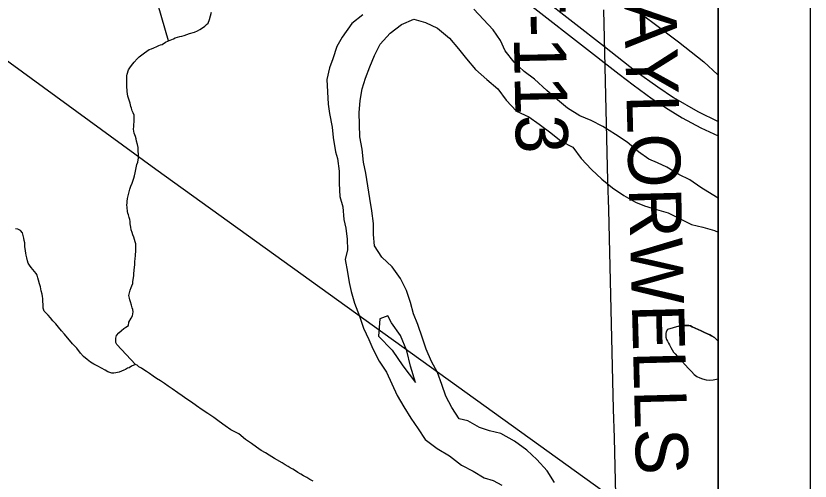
# Model space of a CAD drawing. Extents: x -6.1 to 38, y -7.7 to 22.
# Drawn here: x 8.136 to 9, y 18.932 to 19.438 of the extents above; entities that cross this region are included whole.
import ezdxf

# ---------------------------------------------------------------- set-up
doc = ezdxf.new("R2010")
doc.units = 0
for name, color, linetype in [('GM_X_Corporation', 7, 'Continuous'), ('GM_X_County_Road', 7, 'Continuous'), ('GM_X_Major_River', 7, 'Continuous'), ('GM_X_Minor_Lake', 7, 'Continuous'), ('GM_X_Minor_River', 7, 'Continuous'), ('GM_X_Rail_Line', 7, 'Continuous'), ('GM_X_Township_Road', 7, 'Continuous'), ('GM_X_Township_Road_Text', 7, 'Continuous'), ('GM_X_US_Route', 7, 'Continuous'), ('SH_Data', 7, 'Continuous')]:
    doc.layers.add(name, color=color, linetype=linetype)

msp = doc.modelspace()

# ---------------------------------------------------------------- linework, layer by layer
at = {"layer": 'GM_X_Corporation'}
for points in [[(8.9, 14.85918), (8.9, 19.87135), (8.53815, 19.88018), (8.02661, 19.88922), (8.02125, 19.70471), (8.02079, 19.68982), (8.0189, 19.62846), (7.99279, 18.77986), (7.97287, 17.92154), (7.97183, 17.87641), (7.95308, 17.06692), (7.95307, 17.06643), (7.93594, 16.3267), (7.92512, 16.10977), (7.91657, 15.91251), (7.90988, 15.74002), (7.90533, 15.62285), (7.88899, 15.0865), (7.88923, 14.89059), (8.1023, 14.88375), (8.27757, 14.87811), (8.6137, 14.86789)], [(8.9, 14.68725), (8.9, 19.53649), (8.77571, 19.53237), (8.77312, 19.53228), (6.99327, 19.47331), (6.99349, 19.46054), (7.03821, 16.8882), (7.05054, 16.17866), (7.07262, 15.21743), (7.07601, 15.03919), (7.07603, 15.03845), (7.07902, 14.88093), (7.08348, 14.64684), (7.55487, 14.65733), (8.5875, 14.68029)]]:
    msp.add_lwpolyline(points, close=True, dxfattribs=at)
at = {"layer": 'GM_X_County_Road'}
msp.add_lwpolyline([(8.55884, 19.53655), (8.56055, 19.55141), (8.56401, 19.57385), (8.57684, 19.57004), (8.60433, 19.55739), (8.63363, 19.54294), (8.66313, 19.5289), (8.68078, 19.52027), (8.69356, 19.51458), (8.70948, 19.50683), (8.72684, 19.49888), (8.73496, 19.49599), (8.74219, 19.49218), (8.75161, 19.48737), (8.76586, 19.47794), (8.79435, 19.45647), (8.82886, 19.43058), (8.85695, 19.40972), (8.88424, 19.38804), (8.89909, 19.3742), (8.9, 19.37329)], dxfattribs=at)
at = {"layer": 'GM_X_Major_River'}
for points in [[(8.9, 19.23953), (8.89332, 19.24361), (8.88117, 19.25111), (8.86901, 19.25938), (8.85725, 19.26537), (8.84397, 19.27326), (8.8341, 19.27812), (8.82462, 19.28185), (8.81323, 19.29013), (8.80106, 19.30067), (8.78815, 19.30893), (8.77448, 19.31756), (8.76196, 19.32393), (8.74945, 19.32916), (8.73616, 19.33742), (8.72513, 19.34646), (8.71372, 19.35662), (8.70003, 19.36905), (8.68901, 19.37733), (8.67798, 19.3875), (8.66807, 19.39995), (8.66308, 19.4113), (8.65507, 19.42262), (8.64478, 19.43394), (8.63412, 19.44525)], [(8.51353, 19.43917), (8.50149, 19.42962), (8.491, 19.41476), (8.48501, 19.40448), (8.48056, 19.39118), (8.47722, 19.3813), (8.47428, 19.36876), (8.47567, 19.3417), (8.47721, 19.33185), (8.4799, 19.31669), (8.48107, 19.3057), (8.48376, 19.29016), (8.48568, 19.28259), (8.48761, 19.26894), (8.48765, 19.25567)], [(8.62755, 18.9973), (8.61808, 18.99952), (8.61006, 19.01198), (8.60355, 19.02408), (8.59931, 19.03695), (8.59469, 19.04981), (8.58818, 19.06191), (8.58242, 19.07514), (8.57818, 19.08725), (8.57318, 19.10201), (8.56856, 19.11374), (8.56508, 19.12623), (8.56083, 19.1391), (8.55432, 19.15233), (8.54517, 19.16479), (8.53413, 19.17534), (8.52611, 19.18781), (8.5249, 19.19993), (8.52482, 19.21207), (8.52322, 19.22571), (8.52086, 19.23935), (8.51888, 19.25299), (8.51653, 19.26663), (8.51418, 19.27875), (8.51258, 19.29277), (8.51022, 19.30641), (8.50976, 19.31968), (8.5093, 19.33257), (8.51035, 19.34586), (8.51254, 19.35839), (8.51624, 19.37017), (8.52108, 19.38233), (8.52591, 19.39488), (8.53226, 19.40706), (8.54315, 19.41926), (8.55557, 19.42844), (8.56877, 19.43421), (8.58165, 19.43088), (8.59455, 19.42452), (8.60747, 19.4136), (8.61738, 19.4019), (8.62615, 19.39134), (8.63605, 19.37964), (8.64822, 19.36872), (8.66039, 19.35856), (8.66917, 19.3461), (8.68059, 19.33442), (8.69386, 19.32805), (8.70526, 19.32016), (8.7178, 19.31076), (8.7292, 19.30173), (8.74172, 19.29498), (8.75088, 19.2829), (8.7623, 19.27084), (8.77333, 19.26029), (8.78512, 19.25088), (8.79727, 19.24262), (8.81018, 19.23511), (8.81965, 19.23138), (8.83292, 19.22729), (8.84542, 19.22358), (8.85794, 19.21759), (8.87084, 19.21085), (8.88333, 19.20789), (8.89583, 19.20456), (8.9, 19.20242)], [(8.48765, 19.25567), (8.48845, 19.24127), (8.4915, 19.23028), (8.49268, 19.21626), (8.49498, 19.20679), (8.49614, 19.19504), (8.49656, 19.18328), (8.49406, 19.17281), (8.4968, 19.15917), (8.49838, 19.14781), (8.50072, 19.13796), (8.5042, 19.12547), (8.50959, 19.11109), (8.51421, 19.09823), (8.51996, 19.08575), (8.52419, 19.07553), (8.53108, 19.0623), (8.5391, 19.05022), (8.54485, 19.03774), (8.55061, 19.02488), (8.55787, 19.01241), (8.56551, 19.00032), (8.57353, 18.98862), (8.58117, 18.97691), (8.59409, 18.96713), (8.60775, 18.95925), (8.62068, 18.9491), (8.63357, 18.94273), (8.64534, 18.93522), (8.65519, 18.93225), (8.66468, 18.92738)], [(8.53192, 19.1082), (8.53052, 19.0896), (8.54537, 19.07415), (8.55683, 19.05716), (8.57056, 19.03904)], [(8.57056, 19.03904), (8.56515, 19.05683), (8.56126, 19.07349), (8.55434, 19.09014), (8.54442, 19.1041), (8.54059, 19.11167), (8.53192, 19.1082)], [(8.72176, 18.93039), (8.71374, 18.94286), (8.70269, 18.9553), (8.69166, 18.96547), (8.67836, 18.97525), (8.66356, 18.9835), (8.65107, 18.98645), (8.64045, 18.99018), (8.62755, 18.9973)]]:
    msp.add_lwpolyline(points, dxfattribs=at)
at = {"layer": 'GM_X_Minor_Lake'}
for points in [[(8.85723, 19.10044), (8.84483, 19.09681), (8.84336, 19.09412), (8.84301, 19.09222), (8.84304, 19.09032), (8.84308, 19.08841), (8.84388, 19.08577), (8.84468, 19.08388), (8.84585, 19.082), (8.84703, 19.08012), (8.8486, 19.07711), (8.84979, 19.07447), (8.85135, 19.07221), (8.85328, 19.07035), (8.85561, 19.06734), (8.85794, 19.06473), (8.86065, 19.06173), (8.86762, 19.05425), (8.8711, 19.05089), (8.87381, 19.0479), (8.87689, 19.04567), (8.87995, 19.04421), (8.88301, 19.04312), (8.88683, 19.04205), (8.89063, 19.04174), (8.89443, 19.0418), (8.9, 19.04302)], [(8.9, 19.08436), (8.89935, 19.08486), (8.89588, 19.08784), (8.89281, 19.08969), (8.89089, 19.09079), (8.88821, 19.09189), (8.88515, 19.09335), (8.88132, 19.09519), (8.87825, 19.09665), (8.87481, 19.09811), (8.87174, 19.09958), (8.86982, 19.10068), (8.86792, 19.10103), (8.86526, 19.10098), (8.86108, 19.10091), (8.85729, 19.10046), (8.85723, 19.10044)], [(8.85723, 19.10044), (8.85729, 19.10046), (8.86108, 19.10091), (8.86526, 19.10098), (8.86792, 19.10103), (8.86982, 19.10068), (8.87174, 19.09958), (8.87481, 19.09811), (8.87825, 19.09665), (8.88132, 19.09519), (8.88515, 19.09335), (8.88821, 19.09189), (8.89089, 19.09079), (8.89281, 19.08969), (8.89588, 19.08784), (8.89935, 19.08486), (8.9, 19.08436)]]:
    msp.add_lwpolyline(points, dxfattribs=at)
at = {"layer": 'GM_X_Minor_River'}
for points in [[(8.30178, 19.41067), (8.29082, 19.44964)], [(8.26007, 19.343), (8.25926, 19.34603), (8.25846, 19.3483), (8.25766, 19.35056), (8.25723, 19.35322), (8.25681, 19.35549), (8.25677, 19.35777), (8.25674, 19.35967), (8.25668, 19.36309), (8.25663, 19.36537), (8.25658, 19.36842), (8.25654, 19.37032), (8.2565, 19.3726), (8.25685, 19.3745), (8.25829, 19.37909), (8.2605, 19.38255), (8.26311, 19.38564), (8.26459, 19.38757), (8.26795, 19.39105), (8.27018, 19.39338), (8.2728, 19.3957), (8.2758, 19.39766), (8.27843, 19.39961), (8.28106, 19.40117), (8.28332, 19.40197), (8.28596, 19.40316), (8.28935, 19.40474), (8.29123, 19.40554), (8.29312, 19.40633), (8.29501, 19.40675), (8.29876, 19.40948), (8.30178, 19.41067), (8.30554, 19.41226), (8.30743, 19.41305), (8.30932, 19.41385), (8.31158, 19.41465), (8.31422, 19.41546), (8.3165, 19.41588), (8.31914, 19.41669), (8.32178, 19.41749), (8.3248, 19.41869), (8.33009, 19.4203), (8.33348, 19.42151), (8.33611, 19.42307), (8.33874, 19.42502), (8.34137, 19.42659), (8.34323, 19.42852), (8.3451, 19.43008), (8.34655, 19.43391), (8.34869, 19.44193)], [(8.26594, 19.05868), (8.2458, 19.08037), (8.24462, 19.08264), (8.24458, 19.08454), (8.24454, 19.0872), (8.24524, 19.09025), (8.24785, 19.09296), (8.25084, 19.09568), (8.25346, 19.09762), (8.25533, 19.09918), (8.25834, 19.10113), (8.25866, 19.10456), (8.26123, 19.10917), (8.26271, 19.11148), (8.26305, 19.11376), (8.26339, 19.11605), (8.26297, 19.11833), (8.26255, 19.12022), (8.26174, 19.12325), (8.26054, 19.12665), (8.25974, 19.12892), (8.25932, 19.13081), (8.25889, 19.13384), (8.2596, 19.13652), (8.26031, 19.13957), (8.2614, 19.14226), (8.26212, 19.14417), (8.26322, 19.14685), (8.26318, 19.14875), (8.2642, 19.15523), (8.26416, 19.15751), (8.26448, 19.16094), (8.26479, 19.16475), (8.26514, 19.16666), (8.26511, 19.16856), (8.26545, 19.17047), (8.26577, 19.1739), (8.26609, 19.17694), (8.26606, 19.17884), (8.2664, 19.18075), (8.26637, 19.18265), (8.26632, 19.18569), (8.26628, 19.18797), (8.26624, 19.18987), (8.26582, 19.19215), (8.26501, 19.19479), (8.26421, 19.19706), (8.26303, 19.1997), (8.26222, 19.20235), (8.26141, 19.205), (8.26098, 19.20803), (8.26056, 19.20992), (8.26015, 19.21182), (8.26011, 19.2141), (8.25969, 19.21637), (8.25927, 19.21865), (8.25846, 19.22129), (8.25767, 19.22318), (8.25725, 19.22508), (8.2568, 19.22925), (8.25674, 19.23229), (8.25709, 19.2342), (8.25706, 19.2361), (8.25738, 19.23915), (8.25844, 19.24373), (8.25915, 19.2464), (8.25986, 19.24946), (8.26094, 19.25252), (8.2624, 19.25597), (8.26348, 19.25903), (8.2642, 19.26132), (8.26491, 19.264), (8.26561, 19.26705), (8.26596, 19.26896), (8.26735, 19.27621), (8.26844, 19.27889), (8.26878, 19.28118), (8.26912, 19.28308), (8.26945, 19.28613), (8.26942, 19.28803), (8.269, 19.28993), (8.26896, 19.29221), (8.26891, 19.29487), (8.2681, 19.2979), (8.26727, 19.30168), (8.26685, 19.30396), (8.26604, 19.30661), (8.26525, 19.30849), (8.26446, 19.31038), (8.264, 19.31455), (8.26433, 19.3176), (8.26429, 19.31988), (8.26462, 19.32255), (8.26458, 19.32483), (8.26453, 19.32749), (8.26449, 19.32977), (8.2633, 19.33241), (8.2625, 19.33468), (8.26169, 19.33733), (8.2609, 19.33922), (8.26007, 19.343)], [(8.30592, 19.03202), (8.30168, 19.03499), (8.29745, 19.03795), (8.29322, 19.04092), (8.289, 19.04351), (8.28515, 19.0461), (8.28131, 19.04869), (8.27785, 19.05091), (8.27516, 19.05276), (8.27247, 19.05462), (8.26978, 19.05609), (8.26785, 19.05795), (8.26594, 19.05868), (8.26179, 19.05671), (8.25916, 19.05514), (8.25727, 19.05472), (8.25502, 19.05316), (8.25314, 19.05237), (8.25088, 19.05119), (8.24824, 19.05038), (8.24635, 19.04997), (8.24445, 19.04955), (8.24256, 19.04914), (8.24028, 19.0491), (8.23799, 19.04981), (8.23608, 19.05054), (8.23301, 19.05239), (8.22917, 19.0546), (8.22495, 19.05681), (8.22074, 19.05901), (8.2169, 19.06122), (8.21343, 19.06421), (8.20957, 19.06718), (8.20609, 19.07092), (8.20219, 19.07655), (8.19755, 19.08103), (8.18863, 19.09152), (8.18552, 19.09527), (8.18241, 19.09939), (8.17931, 19.10276), (8.17621, 19.10613), (8.17349, 19.1095), (8.17117, 19.11212), (8.16885, 19.11436), (8.16653, 19.1166), (8.16571, 19.12001), (8.16564, 19.12381), (8.1652, 19.12722), (8.16515, 19.13026), (8.16472, 19.13254), (8.1643, 19.13519), (8.16348, 19.1386), (8.16264, 19.14315), (8.16143, 19.14655), (8.16061, 19.15034), (8.1598, 19.15298), (8.15899, 19.15563), (8.15782, 19.15751), (8.15626, 19.15976), (8.15432, 19.16201), (8.15238, 19.16426), (8.15082, 19.16651), (8.14926, 19.16876), (8.14846, 19.17141), (8.14764, 19.17482), (8.14721, 19.17747), (8.14679, 19.17975), (8.14636, 19.1824), (8.14594, 19.18468), (8.14552, 19.18657), (8.14549, 19.18847), (8.14544, 19.19113), (8.14502, 19.1934), (8.14459, 19.19606), (8.14378, 19.19909), (8.14297, 19.20173), (8.14103, 19.20436), (8.13796, 19.20583), (8.1353, 19.20616)], [(8.45925, 18.93172), (8.4558, 18.93356), (8.45234, 18.93578), (8.4489, 18.93762), (8.44582, 18.93946), (8.44276, 18.94093), (8.44007, 18.94278), (8.43737, 18.94464), (8.43431, 18.9461), (8.432, 18.94758), (8.42893, 18.94943), (8.42547, 18.95165), (8.41741, 18.95645), (8.41434, 18.95829), (8.41127, 18.96014), (8.40743, 18.96235), (8.40283, 18.96493), (8.39782, 18.96864), (8.39205, 18.97272), (8.38552, 18.97717), (8.37857, 18.98313), (8.36976, 18.98753), (8.3636, 18.99199), (8.35707, 18.99643), (8.35129, 19.00089), (8.34475, 19.00534), (8.3386, 19.00941), (8.33245, 19.01348), (8.32706, 19.01757), (8.32169, 19.0209), (8.31668, 19.02461), (8.31207, 19.02795), (8.30592, 19.03202)]]:
    msp.add_lwpolyline(points, dxfattribs=at)
at = {"layer": 'GM_X_Rail_Line'}
msp.add_lwpolyline([(6.19287, 19.69813), (6.21792, 19.65768), (6.25419, 19.613), (6.2935, 19.58374), (6.34004, 19.56589), (6.38312, 19.55199), (6.4273, 19.55367), (6.48418, 19.56365), (6.64401, 19.60019), (6.71957, 19.61741), (6.76764, 19.62675), (6.84656, 19.6383), (7.43863, 19.63931), (7.50222, 19.63795), (7.56146, 19.62521), (7.63701, 19.60108), (7.88712, 19.52077), (7.95726, 19.49994), (8.00695, 19.47618), (8.05679, 19.43987), (8.28809, 19.27109), (8.78458, 18.9138), (8.9, 18.83346)], dxfattribs=at)
at = {"layer": 'GM_X_Township_Road'}
msp.add_lwpolyline([(8.78852, 18.91667), (8.78776, 18.94772), (8.78699, 18.97878), (8.78622, 19.00984), (8.78546, 19.04089), (8.78469, 19.07195), (8.78392, 19.10301), (8.78315, 19.13406), (8.78239, 19.16512), (8.78162, 19.19617), (8.78085, 19.22723), (8.78008, 19.25829), (8.77932, 19.28934), (8.77855, 19.3204), (8.77778, 19.35145), (8.77701, 19.38251), (8.77625, 19.41357), (8.77548, 19.44462)], dxfattribs=at)
at = {"layer": 'GM_X_US_Route'}
for points in [[(7.61518, 19.81605), (7.75881, 19.77617), (7.84307, 19.75294), (8.02146, 19.70417), (8.14551, 19.66955), (8.33405, 19.61765), (8.39877, 19.59963), (8.47646, 19.57811), (8.51624, 19.56662), (8.53644, 19.5601), (8.56055, 19.55141), (8.59116, 19.53752), (8.61201, 19.52623), (8.63133, 19.51472), (8.65305, 19.50017), (8.67195, 19.48583), (8.70734, 19.45869), (8.7762, 19.40454), (8.81092, 19.37747), (8.83437, 19.36054), (8.85131, 19.34924), (8.87781, 19.33405), (8.9, 19.32297)], [(7.61297, 19.80194), (7.8397, 19.73927), (8.021, 19.68928), (8.33536, 19.60266), (8.45631, 19.569), (8.51146, 19.55337), (8.54187, 19.5436), (8.55884, 19.53655), (8.5701, 19.53187), (8.58552, 19.52471), (8.61397, 19.50929), (8.64067, 19.4917), (8.66261, 19.47563), (8.79225, 19.37444), (8.80745, 19.36293), (8.82829, 19.34773), (8.84567, 19.33643), (8.86087, 19.3271), (8.88128, 19.31624), (8.9, 19.30747)]]:
    msp.add_lwpolyline(points, dxfattribs=at)
at = {"layer": 'SH_Data'}
for p, q in [((9, 21), (9, 14)), ((8.9, 20.9), (8.9, 14.1))]:
    msp.add_line(p, q, dxfattribs=at)

# ---------------------------------------------------------------- texts
at = {"layer": 'GM_X_Township_Road_Text'}
for s, height, rotation, p in [('TAYLORWELLS', 0.0568182, 271.48302, (8.79637, 19.49932)), ('T-113', 0.056818, 271.12376, (8.67625, 19.48619))]:
    msp.add_text(s, height=height, rotation=rotation, dxfattribs=at).set_placement(p)

doc.saveas('drawing.dxf')
